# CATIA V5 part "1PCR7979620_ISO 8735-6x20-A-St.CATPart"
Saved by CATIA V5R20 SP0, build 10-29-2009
Part number: 1PCR7979620_ISO 8735-6x20-A-St
Revision: ANY
Definition: UNKNOWN
Nomenclature: 1PCR7979620_ISO 8735-6x20-A-St
Source: Unknown
Bounding box of the stored display mesh (mm): x 0 to 20, y -2.853 to 2.853, z -3 to 3
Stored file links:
  C:\Users\Utente\Desktop\IO LAVORO\3D X SITO CF\CUMSA\3D files RC\RC 123006\1PCR7979620_ISO 8735-6x20-A-St.CATPart
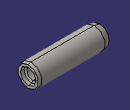
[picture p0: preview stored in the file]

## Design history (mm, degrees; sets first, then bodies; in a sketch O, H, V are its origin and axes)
Body1 "TypeA" (main body)
  Solid1: solid without history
